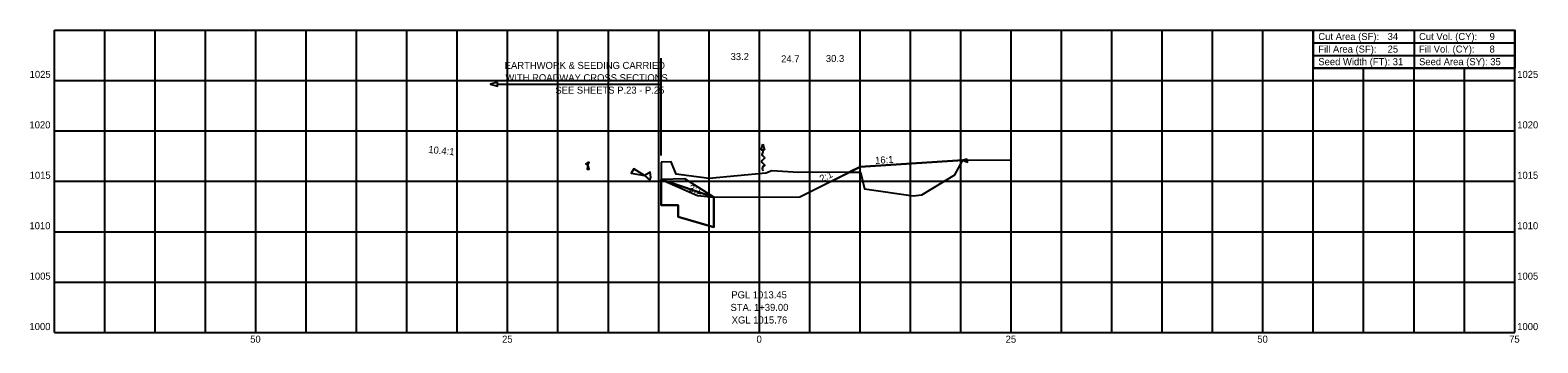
# Model space of a CAD drawing. Extents: x -72 to 77, y 999 to 1030.
import ezdxf

# ---------------------------------------------------------------- set-up
doc = ezdxf.new("R2010")
doc.units = 0
for name, color, linetype in [('Default', 7, 'Continuous'), ('DR_P_Ditch', 7, 'Continuous'), ('DR_P_Headwall', 7, 'Continuous'), ('GK_Drainage_Nodes', 7, 'Continuous'), ('PF_P_Grade_Line', 7, 'Continuous'), ('SH_Data', 7, 'Continuous'), ('SH_Major_Grid_Line', 7, 'Continuous'), ('SH_Text', 7, 'Continuous')]:
    doc.layers.add(name, color=color, linetype=linetype)

msp = doc.modelspace()

# ---------------------------------------------------------------- linework, layer by layer
at = {"layer": 'Default'}
msp.add_circle((75, 1029.98), 0.000417, dxfattribs=at)
msp.add_circle((75, 1029.98), 0.000417, dxfattribs=at)
msp.add_circle((75, 1029.98), 0.000417, dxfattribs=at)
msp.add_circle((75, 1029.98), 0.000417, dxfattribs=at)
msp.add_circle((75, 1029.98), 0.000417, dxfattribs=at)
msp.add_circle((75, 1029.98), 0.000417, dxfattribs=at)
msp.add_circle((75, 1029.98), 0.000417, dxfattribs=at)
msp.add_circle((75, 1029.98), 0.000417, dxfattribs=at)
msp.add_circle((75, 1029.98), 0.000417, dxfattribs=at)
msp.add_circle((75, 1029.98), 0.000417, dxfattribs=at)
msp.add_circle((75, 1029.98), 0.000417, dxfattribs=at)
msp.add_circle((75, 1029.98), 0.000417, dxfattribs=at)
at = {"layer": 'DR_P_Ditch'}
for p, q in [((0.19, 1018.08), (0.35, 1018.68)), ((0.51, 1018.08), (0.19, 1018.08)), ((0.35, 1018.68), (0.51, 1018.08))]:
    msp.add_line(p, q, dxfattribs=at)
msp.add_spline([(0.35, 1018.08), (0.35, 1018.05), (0.3, 1017.81), (0.24, 1017.65), (0.52, 1017.33), (0.21, 1016.97), (0.52, 1016.55), (0.35, 1016.46), (0.35, 1016.05)], degree=3, dxfattribs=at)
at = {"layer": 'DR_P_Headwall'}
for points in [[(-17.05, 1016.85), (-17.22, 1016.73), (-17.04, 1016.64), (-17.1, 1016.2), (-16.9, 1016.2), (-17.04, 1016.64), (-16.92, 1016.87)], [(-9.74, 1016.9), (-9.74, 1015.18), (-4.52, 1013.44), (4, 1013.45), (8.91, 1015.91), (3.89, 1015.89), (1.22, 1016.04), (0.63, 1015.82), (-5, 1015.27), (-8.26, 1015.72), (-8.76, 1016.93)], [(8.91, 1015.91), (10.04, 1015.91), (10.42, 1014.27), (15.28, 1013.56), (16.13, 1013.67), (19.39, 1015.64), (20.21, 1017.08), (10, 1016.45)], [(20.21, 1017.08), (20.66, 1016.89), (20.6, 1017.18)], [(-10.79, 1015.41), (-10.83, 1015.92), (-11.42, 1015.57), (-12.46, 1016.23), (-12.74, 1015.81), (-11.42, 1015.57), (-10.87, 1015.13)], [(-7.39, 1015.23), (-9.74, 1015.18), (-6.14, 1013.58), (-4.52, 1013.44)]]:
    msp.add_lwpolyline(points, close=True, dxfattribs=at)
msp.add_lwpolyline([(-4.52, 1013.44), (4, 1013.45), (10, 1016.45), (20.21, 1017.08), (25, 1017.13)], dxfattribs=at)
at = {"layer": 'GK_Drainage_Nodes'}
for p in [(-9.74, 1015.18), (-4.52, 1013.44)]:
    msp.add_line(p, (-9.74, 1015.18), dxfattribs=at)
msp.add_lwpolyline([(-9.74, 1015.18), (-9.74, 1012.64), (-8.07, 1012.64), (-8.07, 1011.48), (-4.52, 1010.44), (-4.52, 1013.44)], dxfattribs=at)
msp.add_lwpolyline([(-4.52, 1010.44), (-8.07, 1011.48), (-8.07, 1012.64), (-9.74, 1012.64), (-9.74, 1015.18), (-4.52, 1013.44)], close=True, dxfattribs=at)
at = {"layer": 'PF_P_Grade_Line'}
msp.add_lwpolyline([(55, 1029.98), (75, 1029.98), (75, 1026.23), (55, 1026.23)], close=True, dxfattribs=at)
at = {"layer": 'SH_Data'}
for p, q in [((55, 1029.98), (75, 1029.98)), ((55, 1029.98), (55, 1027.48)), ((55, 1028.73), (75, 1028.73)), ((65, 1029.98), (65, 1026.23)), ((75, 1029.98), (75, 1027.48)), ((55, 1027.48), (75, 1027.48)), ((63.3, 1026.86), (63.3, 1026.86)), ((72.95, 1026.86), (72.95, 1026.86))]:
    msp.add_line(p, q, dxfattribs=at)
msp.add_lwpolyline([(55, 1027.48), (55, 1026.23), (75, 1026.23), (75, 1027.48)], dxfattribs=at)
at = {"layer": 'SH_Major_Grid_Line'}
for p, q in [((-70, 1029.98), (75, 1029.98)), ((-70, 1000), (-70, 1029.98)), ((-65, 1000), (-65, 1029.98)), ((-60, 1000), (-60, 1029.98)), ((-55, 1000), (-55, 1029.98)), ((-50, 1000), (-50, 1029.98)), ((-45, 1000), (-45, 1029.98)), ((-40, 1000), (-40, 1029.98)), ((-35, 1000), (-35, 1029.98)), ((-30, 1000), (-30, 1029.98)), ((-25, 1000), (-25, 1029.98)), ((-20, 1000), (-20, 1029.98)), ((-15, 1000), (-15, 1029.98)), ((-10, 1000), (-10, 1029.98)), ((-5, 1000), (-5, 1029.98)), ((0, 1000), (0, 1029.98)), ((5, 1000), (5, 1029.98)), ((10, 1000), (10, 1029.98)), ((15, 1000), (15, 1029.98)), ((20, 1000), (20, 1029.98)), ((25, 1000), (25, 1029.98)), ((30, 1000), (30, 1029.98)), ((35, 1000), (35, 1029.98)), ((40, 1000), (40, 1029.98)), ((45, 1000), (45, 1029.98)), ((50, 1000), (50, 1029.98)), ((55, 1000), (55, 1029.98)), ((75, 1000), (75, 1029.98)), ((60, 1000), (60, 1026.23)), ((65, 1000), (65, 1026.23)), ((70, 1000), (70, 1026.23)), ((-70, 1025), (75, 1025)), ((-70, 1020), (75, 1020)), ((-70, 1015), (75, 1015)), ((-70, 1010), (75, 1010)), ((-70, 1005), (75, 1005)), ((-70, 1000), (75, 1000))]:
    msp.add_line(p, q, dxfattribs=at)
at = {"layer": 'SH_Text'}
for p, q in [((-9.74, 1017.57), (-9.74, 1027.21)), ((-25.98, 1024.63), (-9.74, 1024.63))]:
    msp.add_line(p, q, dxfattribs=at)
msp.add_lwpolyline([(-26.01, 1024.84), (-26.71, 1024.63), (-26.01, 1024.42)], close=True, dxfattribs=at)

# ---------------------------------------------------------------- texts
at = {"layer": 'DR_P_Headwall'}
for s, p in [('33.2', (-2.86, 1027.02)), ('24.7', (2.16, 1026.79)), ('30.3', (6.6, 1026.83))]:
    msp.add_text(s, height=0.7, dxfattribs=at).set_placement(p)
msp.add_text('16:1', height=0.7, rotation=3.5031, dxfattribs=at).set_placement((11.51, 1016.72))
at = {"layer": 'SH_Text'}
for s, p in [('Cut Area (SF):', (55.5, 1029.01)), ('Fill Area (SF):', (55.5, 1027.76)), ('34', (62.38, 1029.01)), ('Cut Vol. (CY):', (65.5, 1029.01)), ('Fill Vol. (CY):', (65.5, 1027.76)), ('9', (72.5, 1029.01)), ('Seed Width (FT): 31', (55.5, 1026.51)), ('25', (62.38, 1027.76)), ('Seed Area (SY): 35', (65.5, 1026.51)), ('8', (72.5, 1027.76)), ('1025', (-72.46, 1025.25)), ('EARTHWORK & SEEDING CARRIED', (-25.29, 1026.14)), ('WITH ROADWAY CROSS SECTIONS', (-25.22, 1024.92)), ('1025', (75.25, 1025.25)), ('SEE SHEETS P.23 - P.25', (-20.26, 1023.69)), ('1020', (-72.48, 1020.25)), ('1020', (75.25, 1020.25)), ('1015', (-72.46, 1015.25)), ('1015', (75.25, 1015.25)), ('1010', (-72.48, 1010.25)), ('1010', (75.25, 1010.25)), ('1005', (-72.46, 1005.25)), ('1005', (75.25, 1005.25)), ('PGL 1013.45', (-2.79, 1003.4)), ('STA. 1+39.00', (-2.87, 1002.15)), ('XGL 1015.76', (-2.75, 1000.9)), ('1000', (-72.48, 1000.25)), ('1000', (75.25, 1000.25)), ('50', (-50.56, 999)), ('25', (-25.55, 999)), ('0', (-0.28, 999)), ('25', (24.45, 999)), ('50', (49.44, 999)), ('75', (74.45, 999))]:
    msp.add_text(s, height=0.7, dxfattribs=at).set_placement(p)
for s, rotation, p in [('10.4:1', 354.4978, (-32.9, 1017.82)), ('2:1', 26.5651, (6.19, 1014.89)), ('3:1', 343.6752, (-7.05, 1014.03))]:
    msp.add_text(s, height=0.7, rotation=rotation, dxfattribs=at).set_placement(p)

doc.saveas('drawing.dxf')
